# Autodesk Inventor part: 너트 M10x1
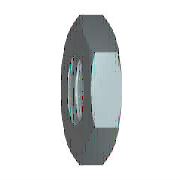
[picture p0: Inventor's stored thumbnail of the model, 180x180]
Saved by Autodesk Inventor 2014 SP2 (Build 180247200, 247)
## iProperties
Created: 2012-02
Part Number: 너트 M10x1
Material: 강철, 연강
Description: 6각 가는 너트 - 이중 모따기(부품 등급 A) - 정밀 나사산
Document SubType Name: Modeling
Standard: JIS B 1181
Designer: mduedu
Standards Organization: JIS
Language: ko-KR
Size Designation: M10x1
Categories: <MemberInstance><Categories><Category DisplayName="조임쇠" InternalName="e4da775c-781d-43d5-af7c-5136215cf5a6" Mnemonic="FSTN"><Category DisplayName="너트" InternalN
Density: 7.86 g/cm^3
Appearance: 강철
IsCustomPart: 1
Author: mduedu
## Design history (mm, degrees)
node "MSC_A1"
node "MSC_PT1"
node "MSC_PT2"
node "MSC_PF1"
body "Solid1"
sketch "스케치1"
  geometry: L1 (8, 4.619)-(8, -4.619); L2 (8, -4.619)-(0, -9.238); L3 (0, -9.238)-(-8, -4.619); L4 (-8, -4.619)-(-8, 4.619); L5 (-8, 4.619)-(0, 9.238); L6 (0, 9.238)-(8, 4.619); C1 r 8 at (0, 0); 2 further points
  constraints: 12 end point, 2 coincident, 1 centre point, 1 tangent, 1 vertical, 11 other
  dimensions: "d0" = 16 diameter of C1 (= ParS)
extrude "돌출1" new body sketch "스케치1" distance "d1" = 5 (= M); taper "d2" = 0 deg
sketch "스케치2"
  geometry: L1 (-8, 4.619)-(0, 9.238) reference; L2 (0, -9.238)-(-8, -4.619) reference; L3 (-8, 4.619)-(8, -4.619); L4 (-8, -4.619)-(8, 4.619); 1 further point
  constraints: 4 end point, 2 midpoint, 2 parallel
hole "구멍1" sketch "스케치2" diameter "d3" = 8.91747; stored, may be unused: countersink angle "d7" = 90 deg, drill point angle "d9" = 118 deg; dims "d4" = 6, "d5" = 4, "d6" = 2, "d8" = 8
chamfer "모따기1" distance "d10" = 0.5 (= 0.5 x PTC); stored, may be unused: second distance "d11" = 2, angle "d12" = 45 deg
revolve "회전1" stored, may be unused: angle "d15" = 90 deg
sketch "스케치3"
  geometry: L1 (-9.238, 5)-(-9.238, 4.285); L2 (-9.238, 4.285)-(-8, 5); L3 (-8, 5)-(-9.238, 5); L4 (-9.238, 0.715)-(-9.238, 0); L5 (-9.238, 0)-(-8, 0); L6 (-8, 0)-(-9.238, 0.715); L7 (0, 6)-(0, -1) reference; L8 (-4.619, 5)-(-9.238, 5) reference; L9 (-4.619, 0)-(-9.238, 0) reference; L10 (-9.238, 0)-(-9.238, 5) reference
  constraints: 12 end point, 4 collinear, 3 perpendicular, 2 equal length, 1 vertical
  dimensions: "d13" = 30 deg angle of L2 L3; "d14" = 8 distance from line of L2.end L7 (= 0.5 x ParS)
other parameters: "ParS" = 16 [user parameter; used in 2 equation terms], "M" = 5 [user parameter; used in 1 equation term], "PTC" = 1 [user parameter; used in 1 equation term], "d17" = 0, "d18" = 0, "d19" = 0, "d20" = 0, "d21" = 0, "d22" = 0, "d23" = 0
